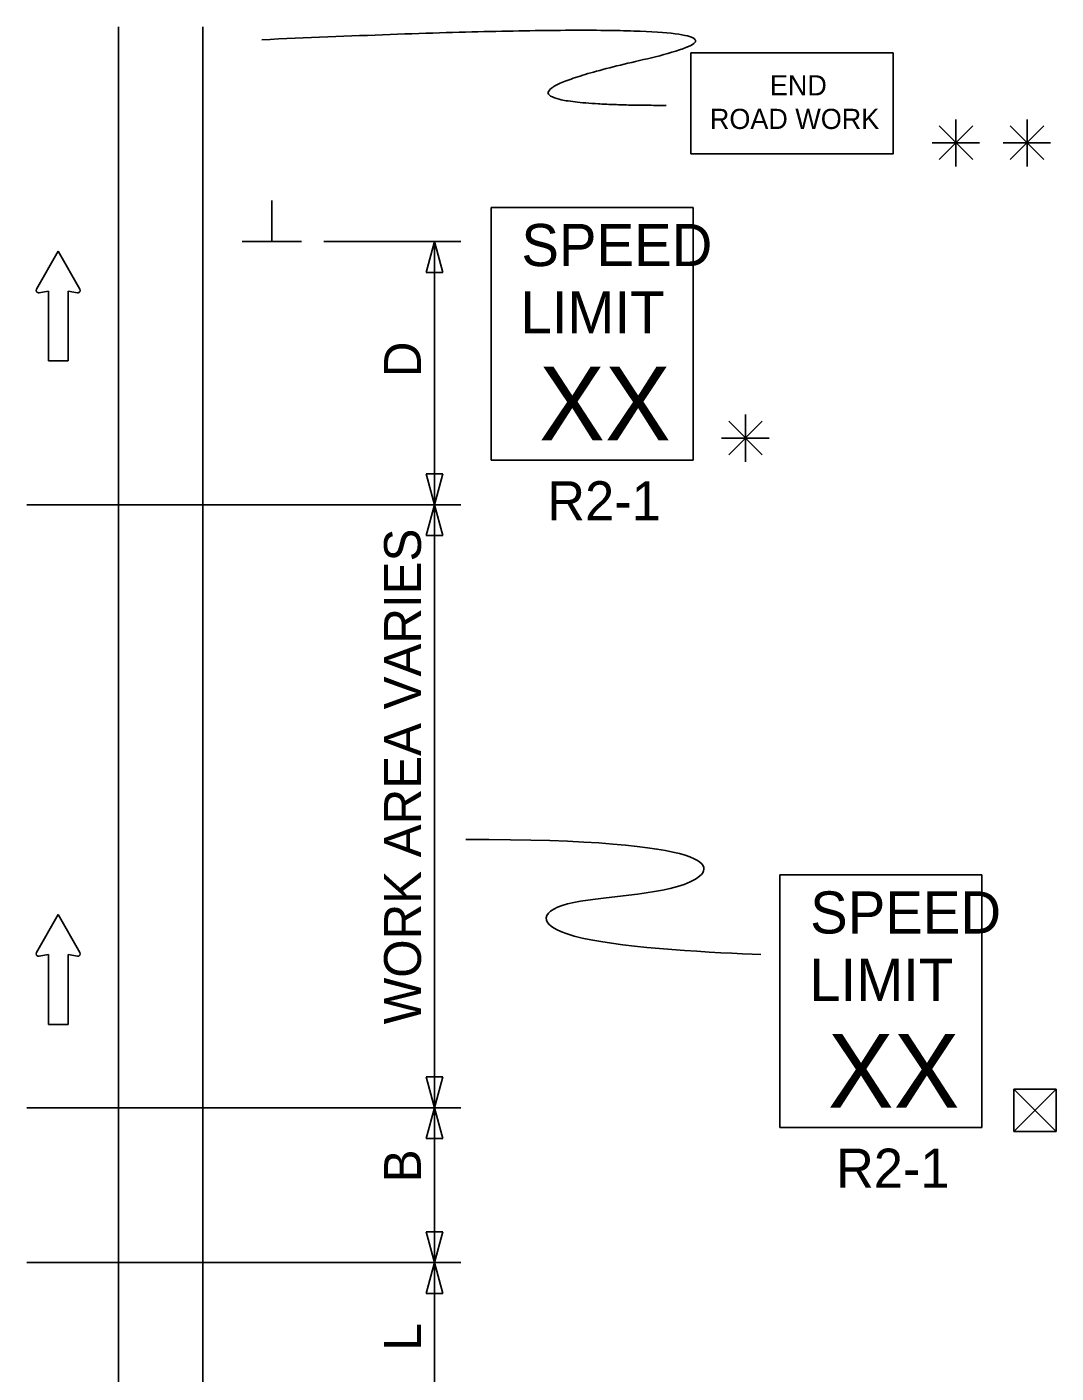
# Model space of a CAD drawing. Extents: x 16730 to 18479, y 5752 to 6927.
# Drawn here: x 16974.3 to 17169.8, y 6671 to 6926.7 of the extents above; entities that cross this region are included whole.
import ezdxf

# ---------------------------------------------------------------- set-up
doc = ezdxf.new("R2010")
doc.units = 0
for name, color, linetype in [('MT_SCRATCH_LEVEL_E', 7, 'Continuous'), ('PAVT_EDGE_EX', 7, 'Continuous'), ('TRAFFIC_SIGNS_PR', 7, 'Continuous'), ('TYPICAL_TEXT_DIMEN_PR', 7, 'Continuous')]:
    doc.layers.add(name, color=color, linetype=linetype)

msp = doc.modelspace()

# ---------------------------------------------------------------- linework, layer by layer
at = {"layer": 'MT_SCRATCH_LEVEL_E'}
for p, q in [((16980.26, 6884.13), (16976.15, 6876.89)), ((16984.41, 6876.89), (16980.26, 6884.13)), ((16976.63, 6876.2), (16978.41, 6876.52)), ((16978.41, 6876.52), (16978.41, 6863.26)), ((16982.15, 6863.26), (16982.15, 6876.52)), ((16982.15, 6876.52), (16983.93, 6876.2)), ((16978.41, 6863.26), (16982.15, 6863.26)), ((16980.26, 6758.11), (16976.15, 6750.87)), ((16984.41, 6750.87), (16980.26, 6758.11)), ((16976.63, 6750.18), (16978.41, 6750.5)), ((16978.41, 6750.5), (16978.41, 6737.24)), ((16982.15, 6737.24), (16982.15, 6750.5)), ((16982.15, 6750.5), (16983.93, 6750.18)), ((16978.41, 6737.24), (16982.15, 6737.24))]:
    msp.add_line(p, q, dxfattribs=at)
for centre, start, end in [((16976.56, 6876.66), 150.4248, 279.9638), ((16984, 6876.66), 260.0362, 29.7731), ((16976.56, 6750.64), 150.4248, 279.9638), ((16984, 6750.64), 260.0362, 29.7731)]:
    msp.add_arc(centre, 0.463, start, end, dxfattribs=at)
at = {"layer": 'PAVT_EDGE_EX'}
for p, q in [((16991.74, 6926.69), (16991.74, 6016.42)), ((17007.74, 6926.69), (17007.74, 6016.42))]:
    msp.add_line(p, q, dxfattribs=at)
at = {"layer": 'TRAFFIC_SIGNS_PR'}
for p, q in [((17062.49, 6892.4), (17100.89, 6892.4)), ((17062.49, 6844.4), (17062.49, 6892.4)), ((17100.89, 6844.4), (17100.89, 6892.4)), ((17062.49, 6844.4), (17100.89, 6844.4)), ((17117.35, 6765.64), (17155.75, 6765.64)), ((17117.35, 6717.64), (17117.35, 6765.64)), ((17155.75, 6717.64), (17155.75, 6765.64)), ((17117.35, 6717.64), (17155.75, 6717.64))]:
    msp.add_line(p, q, dxfattribs=at)
msp.add_lwpolyline([(17100.46, 6902.56), (17138.86, 6902.56), (17138.86, 6921.76), (17100.46, 6921.76)], close=True, dxfattribs=at)
msp.add_open_spline([(17095.74, 6911.79), (17053.23, 6911.79), (17129.75, 6929.21), (17018.96, 6924.27)], degree=2, dxfattribs=at)
at = {"layer": 'TYPICAL_TEXT_DIMEN_PR'}
for p, q in [((17150.79, 6904.69), (17150.79, 6909.14)), ((17164.3, 6904.69), (17164.3, 6909.14)), ((17147.61, 6907.88), (17153.98, 6901.5)), ((17153.98, 6907.88), (17147.61, 6901.5)), ((17161.11, 6907.88), (17167.49, 6901.5)), ((17167.49, 6907.88), (17161.11, 6901.5)), ((17150.79, 6904.69), (17146.26, 6904.69)), ((17150.79, 6904.69), (17153.98, 6904.69)), ((17150.79, 6904.69), (17155.27, 6904.69)), ((17150.79, 6904.69), (17150.79, 6900.19)), ((17164.3, 6904.69), (17159.77, 6904.69)), ((17164.3, 6904.69), (17167.49, 6904.69)), ((17164.3, 6904.69), (17168.78, 6904.69)), ((17164.3, 6904.69), (17164.3, 6900.19)), ((17020.86, 6885.95), (17020.86, 6893.73)), ((17026.49, 6885.95), (17015.24, 6885.95)), ((17056.74, 6885.95), (17030.74, 6885.95)), ((17050.17, 6880.08), (17051.74, 6885.95)), ((17051.74, 6885.95), (17051.74, 6835.95)), ((17051.74, 6885.95), (17053.31, 6880.08)), ((17051.74, 6880.08), (17050.17, 6880.08)), ((17053.31, 6880.08), (17051.74, 6880.08)), ((17110.83, 6848.6), (17110.83, 6853.06)), ((17107.65, 6851.79), (17114.02, 6845.41)), ((17114.02, 6851.79), (17107.65, 6845.41)), ((17110.83, 6848.6), (17106.3, 6848.6)), ((17110.83, 6848.6), (17114.02, 6848.6)), ((17110.83, 6848.6), (17115.31, 6848.6)), ((17110.83, 6848.6), (17110.83, 6844.1)), ((17051.74, 6835.95), (17050.17, 6841.81)), ((17050.17, 6841.81), (17051.74, 6841.81)), ((17051.74, 6841.81), (17053.31, 6841.81)), ((17053.31, 6841.81), (17051.74, 6835.95)), ((17056.74, 6835.95), (16974.34, 6835.95)), ((17050.17, 6830.08), (17051.74, 6835.95)), ((17051.74, 6721.41), (17051.74, 6835.95)), ((17051.74, 6835.95), (17053.31, 6830.08)), ((17051.74, 6830.08), (17050.17, 6830.08)), ((17053.31, 6830.08), (17051.74, 6830.08)), ((17051.74, 6721.41), (17050.17, 6727.27)), ((17050.17, 6727.27), (17051.74, 6727.27)), ((17051.74, 6727.27), (17053.31, 6727.27)), ((17053.31, 6727.27), (17051.74, 6721.41)), ((17161.82, 6724.91), (17169.82, 6716.91)), ((17161.82, 6716.91), (17169.82, 6724.91)), ((17056.74, 6721.41), (16974.34, 6721.41)), ((17050.17, 6715.55), (17051.74, 6721.41)), ((17051.74, 6691.98), (17051.74, 6721.41)), ((17051.74, 6721.41), (17053.31, 6715.55)), ((17051.74, 6715.55), (17050.17, 6715.55)), ((17053.31, 6715.55), (17051.74, 6715.55)), ((17051.74, 6691.98), (17050.17, 6697.84)), ((17050.17, 6697.84), (17051.74, 6697.84)), ((17051.74, 6697.84), (17053.31, 6697.84)), ((17053.31, 6697.84), (17051.74, 6691.98)), ((17056.74, 6691.98), (16974.34, 6691.98)), ((17050.17, 6686.12), (17051.74, 6691.98)), ((17051.74, 6661.42), (17051.74, 6691.98)), ((17051.74, 6691.98), (17053.31, 6686.12)), ((17051.74, 6686.12), (17050.17, 6686.12)), ((17053.31, 6686.12), (17051.74, 6686.12))]:
    msp.add_line(p, q, dxfattribs=at)
msp.add_lwpolyline([(17161.82, 6724.91), (17161.82, 6716.91), (17169.82, 6716.91), (17169.82, 6724.91)], close=True, dxfattribs=at)
msp.add_open_spline([(17057.68, 6772.38), (17106.15, 6772.38), (17106.15, 6761.62), (17071.23, 6761.62), (17071.23, 6752.57), (17105.44, 6750.81), (17113.73, 6750.52)], degree=3, dxfattribs=at)

# ---------------------------------------------------------------- texts
at = {"layer": 'TRAFFIC_SIGNS_PR'}
for s, height, p in [('END', 3.831, (17115.46, 6913.69)), ('ROAD WORK', 3.831, (17104.07, 6907.31)), ('SPEED', 8, (17068.26, 6881.27)), ('LIMIT', 8, (17068.1, 6868.47)), ('XX', 14.031, (17071.61, 6848.16)), ('R2-1', 7.44, (17073.17, 6832.96)), ('SPEED', 8, (17123.11, 6754.5)), ('LIMIT', 8, (17122.95, 6741.7)), ('XX', 14.031, (17126.46, 6721.4)), ('R2-1', 7.44, (17128.02, 6706.2))]:
    msp.add_text(s, height=height, dxfattribs=at).set_placement(p)
at = {"layer": 'TYPICAL_TEXT_DIMEN_PR'}
for s, p in [('D', (17049.18, 6860.17)), ('WORK AREA VARIES', (17049.18, 6737.26)), ('B', (17049.18, 6707.25)), ('L', (17049.18, 6675.28))]:
    msp.add_text(s, height=7, rotation=90, dxfattribs=at).set_placement(p)

doc.saveas('drawing.dxf')
